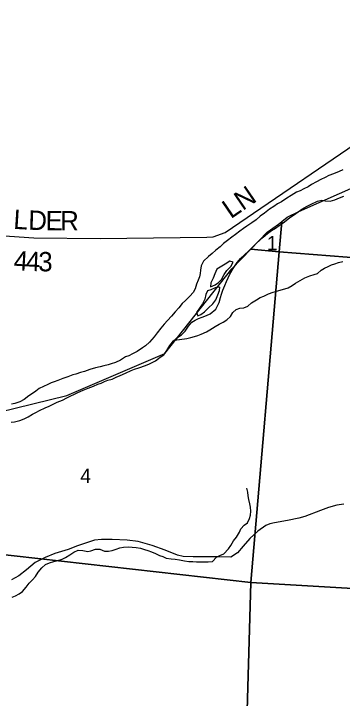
# Model space of a CAD drawing. Extents: x 0 to 34, y 0 to 22.
# Drawn here: x 27.377 to 28.342, y 16.768 to 18.779 of the extents above; entities that cross this region are included whole.
import ezdxf

# ---------------------------------------------------------------- set-up
doc = ezdxf.new("R2010")
doc.units = 0
for name, color, linetype in [('GM_X_Major_River', 7, 'Continuous'), ('GM_X_Minor_River', 7, 'Continuous'), ('GM_X_Section', 7, 'Continuous'), ('GM_X_Section_Text', 7, 'Continuous'), ('GM_X_State_Route', 7, 'Continuous'), ('GM_X_Township_Road', 7, 'Continuous'), ('GM_X_Township_Road_Text', 7, 'Continuous')]:
    doc.layers.add(name, color=color, linetype=linetype)

msp = doc.modelspace()

# ---------------------------------------------------------------- linework, layer by layer
at = {"layer": 'GM_X_Major_River'}
for points in [[(28.3433, 18.3201), (28.3326, 18.3157), (28.3159, 18.3086), (28.3026, 18.3031), (28.292, 18.2975), (28.2787, 18.2916), (28.2661, 18.2849), (28.2517, 18.2771), (28.2414, 18.2704), (28.2292, 18.2645), (28.2182, 18.2589), (28.2075, 18.2541), (28.1919, 18.2452), (28.1794, 18.2366), (28.163, 18.2266), (28.1516, 18.2199), (28.1413, 18.2128), (28.1287, 18.205), (28.1131, 18.193), (28.1012, 18.1837), (28.0887, 18.1736), (28.0764, 18.1642), (28.062, 18.1545), (28.0517, 18.1474), (28.041, 18.14), (28.0284, 18.1306), (28.0174, 18.122), (28.0044, 18.1123), (27.9933, 18.1034), (27.9838, 18.0944), (27.9704, 18.0839), (27.9594, 18.0749), (27.9491, 18.0656), (27.9345, 18.0521), (27.928, 18.0381), (27.9259, 18.0256), (27.9247, 18.0158), (27.9223, 18.006), (27.9192, 17.9961), (27.9138, 17.9841), (27.9098, 17.9712), (27.904, 17.9603), (27.8945, 17.949), (27.8815, 17.9367), (27.8715, 17.9273), (27.8616, 17.9153), (27.8509, 17.9033), (27.8401, 17.8909), (27.829, 17.8781), (27.8191, 17.8665), (27.8095, 17.8552), (27.7988, 17.8413), (27.7895, 17.8296), (27.7761, 17.8146), (27.7643, 17.8038), (27.7548, 17.7978), (27.7392, 17.787), (27.7262, 17.7795), (27.7156, 17.7744), (27.7057, 17.7707), (27.6905, 17.761), (27.676, 17.7547), (27.6635, 17.7507), (27.654, 17.7477), (27.6419, 17.7449), (27.6313, 17.7419), (27.6172, 17.7391), (27.6005, 17.7343), (27.5846, 17.7281), (27.5728, 17.7248), (27.5599, 17.7204), (27.5504, 17.7182), (27.5364, 17.7123), (27.5216, 17.7079), (27.5071, 17.7016), (27.4961, 17.698), (27.4866, 17.6943), (27.4771, 17.6898), (27.4642, 17.6843), (27.452, 17.6776), (27.4417, 17.6701), (27.4318, 17.6634), (27.4219, 17.6563), (27.4078, 17.6459), (27.3949, 17.6392), (27.3804, 17.634), (27.3702, 17.6319)], [(27.3693, 17.5796), (27.3791, 17.5806), (27.395, 17.5846), (27.4076, 17.5894), (27.4197, 17.5953), (27.4323, 17.6024), (27.4422, 17.6076), (27.4525, 17.6131), (27.4696, 17.6217), (27.481, 17.6265), (27.4928, 17.632), (27.5049, 17.638), (27.5205, 17.6435), (27.5331, 17.6502), (27.5658, 17.6661), (27.5806, 17.6731), (27.5954, 17.679), (27.611, 17.6853), (27.6243, 17.6908), (27.6341, 17.6941), (27.644, 17.6986), (27.6535, 17.7023), (27.666, 17.7059), (27.6778, 17.7111), (27.6896, 17.7163), (27.7056, 17.7233), (27.7219, 17.7307), (27.7318, 17.7344), (27.7447, 17.7388), (27.7637, 17.7458), (27.7755, 17.7509), (27.793, 17.7595), (27.8074, 17.7703), (27.8181, 17.7774), (27.8269, 17.7898), (27.8358, 17.8041), (27.8462, 17.8176), (27.8576, 17.8281), (27.8698, 17.8359), (27.8801, 17.8468), (27.8901, 17.8615), (27.9001, 17.8724), (27.9104, 17.8791), (27.9202, 17.8835), (27.9305, 17.8872), (27.943, 17.892), (27.9544, 17.8972), (27.9708, 17.9106), (27.9759, 17.9204), (27.9801, 17.931), (27.9848, 17.9454), (27.9876, 17.9552), (27.9911, 17.9665), (27.9969, 17.9801), (28.002, 17.9918), (28.007, 18.0031), (28.012, 18.0141), (28.0213, 18.0303), (28.0336, 18.0476), (28.0432, 18.0596), (28.055, 18.0708), (28.0672, 18.0824), (28.0799, 18.0948), (28.0898, 18.1049), (28.0994, 18.1135), (28.1093, 18.1225), (28.1223, 18.1334), (28.1345, 18.142), (28.1463, 18.149), (28.1569, 18.1565), (28.168, 18.1643), (28.1775, 18.1718), (28.1882, 18.1804), (28.1989, 18.1871), (28.2126, 18.1972), (28.2233, 18.2043), (28.2389, 18.2132), (28.2484, 18.2184), (28.2689, 18.2284), (28.2818, 18.2309), (28.292, 18.2293), (28.3064, 18.228), (28.3196, 18.2316), (28.3341, 18.2379), (28.3462, 18.2427)], [(27.9731, 18.0288), (27.9672, 18.0152), (27.9629, 18.0019), (27.9556, 17.9887), (27.9554, 17.9766), (27.9688, 17.9825), (27.9783, 17.9889), (27.9871, 17.9986), (27.9953, 18.0129), (28.0034, 18.025), (28.0149, 18.0366), (28.0218, 18.0495), (28.0116, 18.0522), (27.9983, 18.0429)], [(27.9983, 18.0429), (27.9731, 18.0288)], [(27.9462, 17.9646), (27.9415, 17.9536), (27.938, 17.94), (27.931, 17.9268), (27.9225, 17.9136), (27.9136, 17.9008), (27.9173, 17.8913), (27.9268, 17.8949), (27.9372, 17.9036), (27.9494, 17.9148), (27.9617, 17.9264), (27.9702, 17.9388), (27.9764, 17.9532), (27.9815, 17.966), (27.9827, 17.9759), (27.969, 17.9734), (27.9557, 17.9682)], [(27.9557, 17.9682), (27.9462, 17.9646)]]:
    msp.add_lwpolyline(points, dxfattribs=at)
at = {"layer": 'GM_X_Minor_River'}
for points in [[(27.8489, 17.8201), (27.8851, 17.8245), (27.8969, 17.8274), (27.9075, 17.831), (27.9174, 17.834), (27.9273, 17.8373), (27.9429, 17.8447), (27.9532, 17.8506), (27.9689, 17.8603), (27.9803, 17.8674), (27.9925, 17.8729), (28.0032, 17.8796), (28.0136, 17.8894), (28.0205, 17.9011), (28.0301, 17.9105), (28.0411, 17.9141), (28.0529, 17.9151), (28.0643, 17.9195), (28.0758, 17.93), (28.0899, 17.9386), (28.101, 17.9449), (28.1113, 17.949), (28.1254, 17.956), (28.1391, 17.9608), (28.1527, 17.9648), (28.1622, 17.9674), (28.1736, 17.9703), (28.1832, 17.9736), (28.195, 17.9803), (28.2049, 17.9874), (28.2186, 17.9952), (28.232, 18.0034), (28.2465, 18.0093), (28.2598, 18.0125), (28.2693, 18.0162), (28.2804, 18.0252), (28.2899, 18.0319), (28.3002, 18.0367), (28.3101, 18.0412), (28.3196, 18.0437), (28.331, 18.0478), (28.3432, 18.0514)], [(27.3724, 17.0657), (27.3827, 17.0693), (27.3934, 17.0753), (27.4033, 17.0824), (27.4137, 17.0948), (27.4229, 17.1068), (27.4325, 17.1158), (27.4413, 17.1256), (27.4487, 17.1384), (27.4595, 17.1519), (27.4702, 17.1609), (27.482, 17.1661), (27.4945, 17.1705), (27.5067, 17.1734), (27.5192, 17.1771), (27.5291, 17.1819), (27.5414, 17.1893), (27.5536, 17.1975), (27.5665, 17.2035), (27.5802, 17.2025), (27.5945, 17.1997), (27.604, 17.2011), (27.6177, 17.2059), (27.6299, 17.2065), (27.6434, 17.2003), (27.6556, 17.2005), (27.6658, 17.2027), (27.6776, 17.2067), (27.689, 17.21), (27.6993, 17.2118), (27.7137, 17.2128), (27.7247, 17.2126), (27.7368, 17.211), (27.7493, 17.2089), (27.761, 17.2058), (27.7708, 17.2022), (27.7817, 17.1983), (27.793, 17.1936), (27.8051, 17.1878), (27.8149, 17.1843), (27.8247, 17.18), (27.8395, 17.1779), (27.8508, 17.1766), (27.8637, 17.175), (27.8784, 17.1725), (27.8917, 17.1705), (27.9034, 17.1696), (27.914, 17.1691), (27.9383, 17.1688), (27.9478, 17.1691), (27.961, 17.1701), (27.9726, 17.1832), (27.9821, 17.1877), (27.9943, 17.1925), (28.0077, 17.2071), (28.0142, 17.2173), (28.0227, 17.2305), (28.0312, 17.2417), (28.0397, 17.2561), (28.0436, 17.2659), (28.0543, 17.2764), (28.0639, 17.2835), (28.0693, 17.2963), (28.0729, 17.3062), (28.0738, 17.3175), (28.072, 17.3293), (28.0706, 17.3392), (28.0677, 17.3518), (28.0659, 17.3632), (28.0642, 17.3734), (28.0616, 17.3856)]]:
    msp.add_lwpolyline(points, dxfattribs=at)
at = {"layer": 'GM_X_Section'}
for points in [[(29.1658, 18.7281), (29.1178, 18.0184), (28.5033, 18.0906), (28.5064, 18.0521), (28.157, 18.0791), (28.1647, 18.1688), (28.1804, 18.1807), (28.214, 18.1975), (28.5041, 18.3264), (28.8554, 18.5398)], [(28.073, 18.087), (28.1217, 18.1369), (28.1543, 18.1609), (28.1647, 18.1688), (28.157, 18.0791)], [(28.073, 18.087), (28.157, 18.0791), (28.0732, 17.1088), (27.0998, 17.2184), (27.0604, 17.2208), (27.1053, 17.8104), (27.2042, 17.652), (27.2781, 17.5952), (27.3324, 17.6084), (27.5334, 17.6576), (27.8207, 17.7804), (28.0174, 18.0299)], [(28.157, 18.0791), (28.5064, 18.0521), (28.5033, 18.0906), (29.1178, 18.0184), (29.0528, 17.0493), (28.8721, 17.0617), (28.0732, 17.1088)], [(27.0998, 17.2184), (28.0732, 17.1088), (28.0465, 16.1852), (28.0441, 16.1595), (27.0114, 16.2186)], [(28.0732, 17.1088), (28.8721, 17.0617), (28.8121, 16.0697), (28.0465, 16.1852)]]:
    msp.add_lwpolyline(points, close=True, dxfattribs=at)
at = {"layer": 'GM_X_State_Route'}
msp.add_lwpolyline([(28.3461, 17.338), (28.326, 17.3355), (28.3016, 17.3282), (28.2778, 17.3194), (28.2323, 17.3026), (28.2141, 17.2978), (28.1809, 17.29), (28.1433, 17.2835), (28.1296, 17.2807), (28.1176, 17.2757), (28.0937, 17.2594), (28.0706, 17.2373), (28.0513, 17.2149), (28.0339, 17.1958), (28.0146, 17.1829), (27.9791, 17.1834), (27.9432, 17.1834), (27.9037, 17.1842), (27.8748, 17.1847), (27.8584, 17.1884), (27.8222, 17.2033), (27.7839, 17.2174), (27.743, 17.2287), (27.7098, 17.2332), (27.6666, 17.2342), (27.6349, 17.2342), (27.6143, 17.2325), (27.5647, 17.2164), (27.537, 17.2055), (27.4979, 17.1936), (27.4697, 17.1822), (27.4399, 17.1676), (27.4145, 17.1459), (27.3922, 17.1276), (27.371, 17.1166)], dxfattribs=at)
at = {"layer": 'GM_X_Township_Road'}
msp.add_lwpolyline([(27.1485, 18.1572), (27.153, 18.1629), (27.1629, 18.1674), (27.1753, 18.1651), (27.1953, 18.1509), (27.2498, 18.1328), (27.436, 18.1203), (27.6307, 18.1188), (27.944, 18.1227), (27.9625, 18.1237), (27.9982, 18.1364), (28.4629, 18.4537), (28.5488, 18.5052), (28.6466, 18.5805), (28.777, 18.6591), (28.8222, 18.6888), (28.8454, 18.7016), (28.8686, 18.7105), (28.8906, 18.7294), (28.9056, 18.7513), (28.9087, 18.7665), (28.9065, 18.7786)], dxfattribs=at)

# ---------------------------------------------------------------- texts
at = {"layer": 'GM_X_Section_Text'}
for s, p in [('1', (28.1205, 18.084)), ('4', (27.5726, 17.401))]:
    msp.add_text(s, height=0.0419, rotation=0, dxfattribs=at).set_placement(p)
at = {"layer": 'GM_X_Township_Road_Text'}
for s, height, rotation, p in [('LN', 0.05682, 34.4017, (28.0146, 18.1749)), ('L', 0.0568, 356.4958, (27.3749, 18.1471)), ('D', 0.0568, 358.1778, (27.4191, 18.1444)), ('E', 0.0568, 359.5182, (27.4705, 18.1428)), ('R', 0.0568, 359.6375, (27.5132, 18.1425)), ('4', 0.0568, 356.5877, (27.3758, 18.026)), ('4', 0.0568, 357.5006, (27.4118, 18.0239)), ('3', 0.0568, 359.4895, (27.4489, 18.0223))]:
    msp.add_text(s, height=height, rotation=rotation, dxfattribs=at).set_placement(p)

doc.saveas('drawing.dxf')
